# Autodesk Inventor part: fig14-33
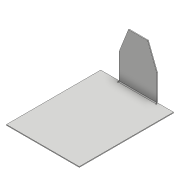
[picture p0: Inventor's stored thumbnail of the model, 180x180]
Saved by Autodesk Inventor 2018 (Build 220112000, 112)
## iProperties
Created: 2017-05
Part Number: fig14-33
Material: Generic
Document SubType Name: Sheet Metal
Designer: CADCIM 00
Density: 1 g/cm^3
Sheet Metal Rule: Default_mm
Appearance: Default
Author: CADCIM 00
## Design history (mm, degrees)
node "Face1"
  sketch "Sketch1"
    geometry: L1 (0, 0)-(45.649, 0); L2 (45.649, 0)-(45.649, 59.054); L3 (45.649, 59.054)-(0, 59.054); L4 (0, 59.054)-(0, 0)
    constraints: 8 end point, 2 parallel, 1 horizontal, 1 perpendicular
node "Face2"
  sketch "Sketch2"
    geometry: L1 (12.162, -17.144)-(17.899, -31.705); L2 (17.899, -31.705)-(29.912, -31.705); L3 (29.912, -31.705)-(35.56, -17.144); L4 (35.56, -17.144)-(12.162, -17.144); 1 further point
    constraints: 8 end point, 1 horizontal, 1 parallel
body "Solid1"
face "Plate1" dims "d0" = 0.5 (= Thickness)
face "Plate2" dims "d0" = 0.5 (= Thickness), "d1" = 0.5 (= BendRadius), "d2" = 0.5 (= BendReliefWidth), "d4" = 1 (= MinimumRemnant)
bend "Bend1" dims "d0" = 0.5 (= Thickness), "d1" = 0.5 (= BendRadius), "d2" = 0.5 (= BendReliefWidth), "d3" = 0.25 (= BendReliefDepth), "d4" = 1 (= MinimumRemnant), "d5" = 0.5 (= TransitionRadius), "SeamGap" = 0.01
other parameters: "Thickness" = 0.5, "BendRadius" = 0.5 (= Thickness), "BendReliefWidth" = 0.5 (= Thickness), "BendReliefDepth" = 0.25 (= 0.5 x Thickness), "CornerReliefSize" = 2 (= 4 x Thickness), "MinimumRemnant" = 1 (= 2 x Thickness), "TransitionRadius" = 0.5 (= BendRadius), "JacobiRadiusSize" = 0.5 (= BendRadius), "GapSize" = 0.5 (= Thickness)
